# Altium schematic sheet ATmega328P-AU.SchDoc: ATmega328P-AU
size 296 x 210 mm; Revision: 1.0; DocumentSize: A4
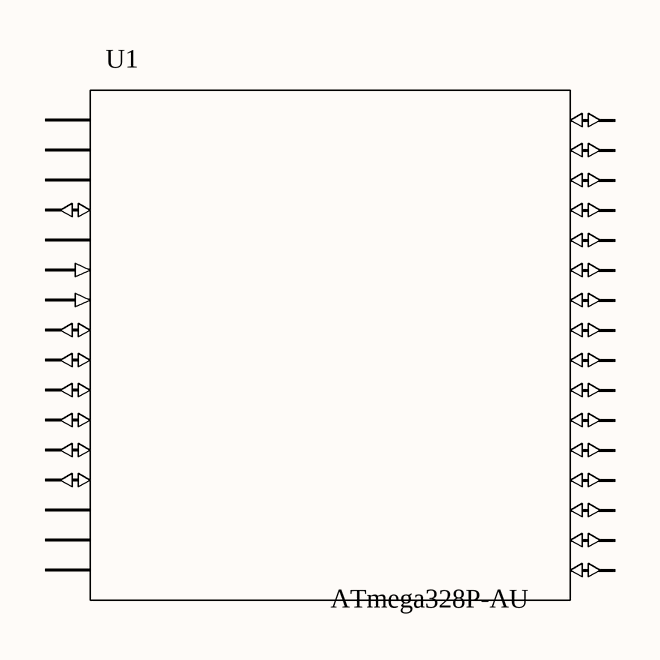
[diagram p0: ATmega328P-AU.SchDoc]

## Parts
U1  value ATmega328P-AU

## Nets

Not connected (* = marked no-connect by the designer): U1 1(PD3/INT1/OC2B/PCINT19) 2(PD4/T0/XCK/PCINT20) 3(GND) 4(VCC) 5(GND) 6(VCC) 7(PB6/XTAL1/TOSC1/PCINT6) 8(PB7/XTAL2/TOSC2/PCINT7) 9(PD5/T1/OC0B/PCINT21) 10(PD6/AIN0/OC0A/PCINT22) 11(PD7/AIN1/PCINT23) 12(PB0/ICP1/CLKO/PCINT0) 13(PB1/OC1A/PCINT1) 14(PB2/SS/OC1B/PCINT2) 15(PB3/MOSI/OC2A/PCINT3) 16(PB4/MISO/PCINT4) 17(PB5/SCK/PCINT5) 18(AVCC) 19(ADC6) 20(AREF) 21(GND) 22(ADC7) 23(PC0/ADC0/PCINT8) 24(PC1/ADC1/PCINT9) 25(PC2/ADC2/PCINT10) 26(PC3/ADC3/PCINT11) 27(PC4/ADC4/SDA/PCINT12) 28(PC5/ADC5/SCL/PCINT13) 29(PC6/RESET/PCINT14) 30(PD0/RXD/PCINT16) 31(PD1/TXD/PCINT17) 32(PD2/INT0/PCINT18)

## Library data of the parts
U1 = ATmega328P-AU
